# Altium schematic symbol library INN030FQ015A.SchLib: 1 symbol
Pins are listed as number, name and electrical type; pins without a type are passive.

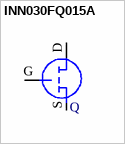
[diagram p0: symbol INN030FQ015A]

## INN030FQ015A
designator Q
footprint FCQFN 5*4 (INN040FQ015A)
pins: D, G, S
